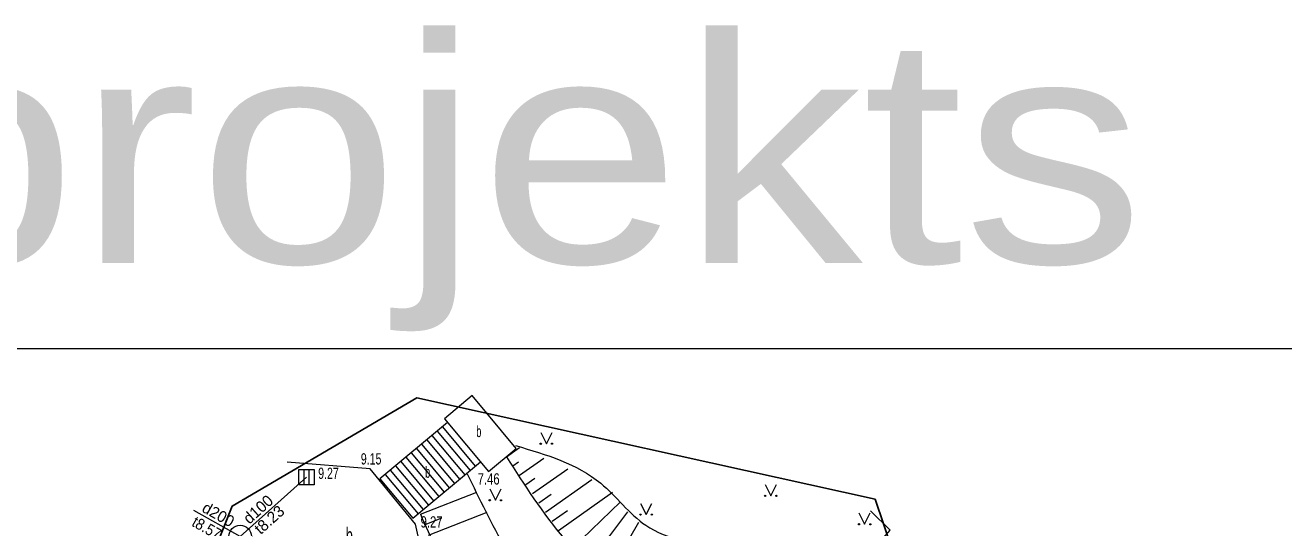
# Model space of a CAD drawing. Extents: x -1320 to -1174, y 762 to 862.
# Drawn here: x -1267.4 to -1211.6, y 839.7 to 862 of the extents above; entities that cross this region are included whole.
import ezdxf
from ezdxf.enums import TextEntityAlignment as Align

# ---------------------------------------------------------------- set-up
doc = ezdxf.new("R2010")
doc.units = 0
doc.header["$LTSCALE"] = 0.2
for name, color, linetype, lineweight in [('1', 7, 'Continuous', 13), ('11', 7, 'Continuous', 35), ('2', 7, 'Continuous', 13), ('22', 7, 'Continuous', 13), ('28', 7, 'Continuous', 13), ('3', 7, 'Continuous', 13), ('5', 7, 'Continuous', 13), ('56', 7, 'Continuous', 13), ('62', 7, 'Continuous', 13), ('63', 7, 'Continuous', 13)]:
    doc.layers.add(name, color=color, linetype=linetype, lineweight=lineweight)
for name, color, linetype in [('10', 7, 'Continuous'), ('15', 7, 'Continuous'), ('32', 7, 'Continuous'), ('8', 7, 'Continuous')]:
    doc.layers.add(name, color=color, linetype=linetype)

msp = doc.modelspace()

# ---------------------------------------------------------------- linework, layer by layer
at = {"layer": '1'}
for p, q in [((-1246.042, 842.876), (-1245.457, 843.29)), ((-1245.465, 842.059), (-1244.391, 842.818)), ((-1245.754, 842.468), (-1245.505, 842.643)), ((-1244.889, 841.242), (-1243.325, 842.347)), ((-1245.177, 841.651), (-1244.781, 841.93)), ((-1244.312, 840.426), (-1242.259, 841.875)), ((-1249.854, 840.332), (-1247.358, 841.312)), ((-1244.6, 840.834), (-1244.058, 841.217)), ((-1243.735, 839.609), (-1241.338, 841.302)), ((-1243.124, 838.819), (-1240.995, 840.873)), ((-1249.671, 839.867), (-1248.908, 840.166)), ((-1249.489, 839.401), (-1246.898, 840.418)), ((-1244.023, 840.017), (-1243.337, 840.502)), ((-1242.368, 838.166), (-1240.664, 840.435)), ((-1241.546, 837.596), (-1240.185, 839.986))]:
    msp.add_line(p, q, dxfattribs=at)
for points in [[(-1246.042, 842.876), (-1243.477, 839.245), (-1241.649, 837.661), (-1239.903, 836.815), (-1239.03, 836.023)], [(-1249.854, 840.332), (-1248.633, 837.222), (-1247.863, 834.323), (-1246.685, 832.854), (-1244.862, 832.816), (-1243.584, 833.187), (-1243.096, 833.394), (-1242.798, 833.227)]]:
    msp.add_spline(points, degree=3, dxfattribs=at)
at = {"layer": '2'}
msp.add_lwpolyline([(-1231.313, 837.008), (-1229.045, 839.621), (-1229.917, 840.478)], dxfattribs=at)
at = {"layer": '22'}
msp.add_lwpolyline([(-1182.029, 847.654), (-1319.805, 847.654), (-1319.805, 776.291), (-1182.029, 776.291)], close=True, dxfattribs=at)
at = {"layer": '28'}
for p, q in [((-1255.01, 842.311), (-1255.01, 841.636)), ((-1254.785, 842.311), (-1254.785, 841.636))]:
    msp.add_line(p, q, dxfattribs=at)
msp.add_lwpolyline([(-1255.235, 842.311), (-1254.56, 842.311), (-1254.56, 841.636), (-1255.235, 841.636)], close=True, dxfattribs=at)
msp.add_circle((-1257.833, 839.3432), 0.5, dxfattribs=at)
at = {"layer": '3'}
msp.add_lwpolyline([(-1254.897, 841.973), (-1257.833, 839.343), (-1259.889, 840.496)], dxfattribs=at)
at = {"layer": '5'}
for points in [[(-1244.523, 843.953), (-1244.273, 843.453), (-1244.023, 843.953)], [(-1246.781, 841.448), (-1246.531, 840.948), (-1246.281, 841.448)], [(-1234.585, 841.642), (-1234.335, 841.142), (-1234.085, 841.642)], [(-1240.102, 840.813), (-1239.852, 840.313), (-1239.602, 840.813)], [(-1230.429, 840.386), (-1230.179, 839.886), (-1229.929, 840.386)]]:
    msp.add_lwpolyline(points, dxfattribs=at)
for centre, radius in [((-1244.5232, 843.4526), 0.028), ((-1244.0232, 843.4526), 0.0263), ((-1234.5854, 841.1418), 0.028), ((-1234.0854, 841.1418), 0.0263), ((-1246.7813, 840.9476), 0.028), ((-1246.2813, 840.9476), 0.0263), ((-1240.1023, 840.313), 0.028), ((-1239.6023, 840.313), 0.0263), ((-1230.4289, 839.8859), 0.028), ((-1229.9289, 839.8859), 0.0263)]:
    msp.add_circle(centre, radius, dxfattribs=at)
at = {"layer": '56'}
for p, q in [((-1249.109, 844.012), (-1247.652, 842.263)), ((-1248.878, 844.204), (-1247.421, 842.455)), ((-1249.8, 843.436), (-1248.343, 841.687)), ((-1249.57, 843.628), (-1248.113, 841.879)), ((-1249.339, 843.82), (-1247.882, 842.071)), ((-1250.492, 842.86), (-1249.035, 841.111)), ((-1250.261, 843.052), (-1248.804, 841.303)), ((-1250.031, 843.244), (-1248.574, 841.495)), ((-1251.183, 842.284), (-1249.726, 840.535)), ((-1250.953, 842.476), (-1249.496, 840.727)), ((-1250.722, 842.668), (-1249.265, 840.919)), ((-1251.414, 842.092), (-1249.957, 840.343))]:
    msp.add_line(p, q, dxfattribs=at)
msp.add_lwpolyline([(-1247.556, 845.583), (-1248.784, 844.56), (-1246.839, 842.225), (-1245.611, 843.247)], close=True, dxfattribs=at)
msp.add_lwpolyline([(-1248.648, 844.396), (-1251.644, 841.9), (-1250.187, 840.151), (-1247.191, 842.647)], dxfattribs=at)
at = {"layer": '62'}
for points in [[(-1245.633, 843.367), (-1241.867, 841.702), (-1239.875, 839.845), (-1236.383, 838.863)], [(-1241.123, 835.019), (-1244.625, 836.811), (-1246.059, 838.788), (-1247.767, 842.107)]]:
    msp.add_spline(points, degree=3, dxfattribs=at)
at = {"layer": '63', "lineweight": 25}
msp.add_lwpolyline([(-1251.428, 785.238), (-1264.287, 784.95), (-1270.386, 788.761), (-1278.142, 789.522), (-1278.429, 820.376), (-1260.692, 834.371), (-1258.181, 840.695), (-1250.014, 845.483), (-1229.719, 840.992), (-1227.821, 835.408), (-1218.992, 825.806), (-1239.144, 811.691), (-1246.246, 803.626), (-1250.024, 795.415), (-1251.371, 785.665)], close=True, dxfattribs=at)
at = {"layer": '63'}
msp.add_lwpolyline([(-1243.096, 833.394), (-1244.191, 832.814), (-1245.103, 832.332), (-1246.012, 831.935), (-1246.99, 832.03), (-1247.991, 832.758), (-1248.872, 833.799), (-1249.154, 834.641), (-1249.207, 835.507), (-1249.314, 836.514), (-1250.061, 839.893), (-1252.08, 842.338), (-1255.758, 842.638)], dxfattribs=at)

# ---------------------------------------------------------------- texts
at = {"layer": '1', "width": 1.2}
msp.add_text('projekts', height=10, dxfattribs=at).set_placement((-1245.887, 851.447), align=Align.CENTER)
at = {"layer": '10', "width": 0.6}
msp.add_text('b', height=0.7, dxfattribs=at).set_placement((-1252.996, 839.038), align=Align.CENTER)
at = {"layer": '11'}
for s, rotation, p in [('d100', 41.853, (-1256.8718, 840.3597)), ('d200', 330.715, (-1258.9208, 840.1022)), ('t8.23', 41.853, (-1256.3733, 839.901))]:
    msp.add_text(s, height=0.5, rotation=rotation, dxfattribs=at).set_placement(p, align=Align.CENTER)
at = {"layer": '11', "width": 0.9}
msp.add_text('t8.57', height=0.5, rotation=330.715, dxfattribs=at).set_placement((-1259.4318, 839.5063), align=Align.CENTER)
at = {"layer": '15', "width": 0.6}
for p in [(-1247.377, 843.746), (-1249.64, 841.945)]:
    msp.add_text('b', height=0.5, dxfattribs=at).set_placement(p)
at = {"layer": '32', "width": 0.7}
msp.add_text('9.27', height=0.5, dxfattribs=at).set_placement((-1254.378, 841.893))
at = {"layer": '8'}
for s, width, p in [(' 9.15', 0.7, (-1252.619, 842.532)), (' 7.46', 0.75, (-1247.458, 841.644)), (' 9.27', 0.75, (-1249.984, 839.74))]:
    msp.add_text(s, height=0.5, dxfattribs=dict(at, width=width)).set_placement(p)

doc.saveas('drawing.dxf')
